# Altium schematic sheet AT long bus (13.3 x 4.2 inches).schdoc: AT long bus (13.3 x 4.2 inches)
size A; Organization: Organization; Address1: Address1; Address2: Address2; Address3: Address3; Address4: Address4; DocumentNumber: 1; Revision: 0; SheetNumber: 2; SheetTotal: 2
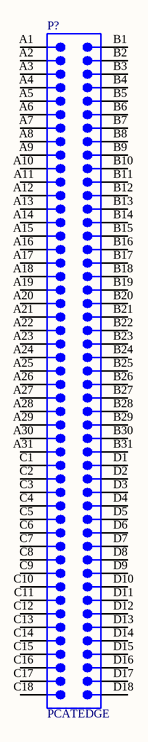
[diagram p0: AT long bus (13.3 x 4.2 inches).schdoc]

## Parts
P?  PCATEDGE  [PCATEDGE]

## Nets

Not connected (* = marked no-connect by the designer): P? A1 A2 A3 A4 A5 A6 A7 A8 A9 A10 A11 A12 A13 A14 A15 A16 A17 A18 A19 A20 A21 A22 A23 A24 A25 A26 A27 A28 A29 A30 A31 B1 B2 B3 B4 B5 B6 B7 B8 B9 B10 B11 B12 B13 B14 B15 B16 B17 B18 B19 B20 B21 B22 B23 B24 B25 B26 B27 B28 B29 B30 B31 C1 C2 C3 C4 C5 C6 C7 C8 C9 C10 C11 C12 C13 C14 C15 C16 C17 C18 D1 D2 D3 D4 D5 D6 D7 D8 D9 D10 D11 D12 D13 D14 D15 D16 D17 D18

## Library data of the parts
P? = PCATEDGE: Card, 98-Position; Text Field6: Alternate Layout Available; Text Field7: Published 14-Feb-2002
